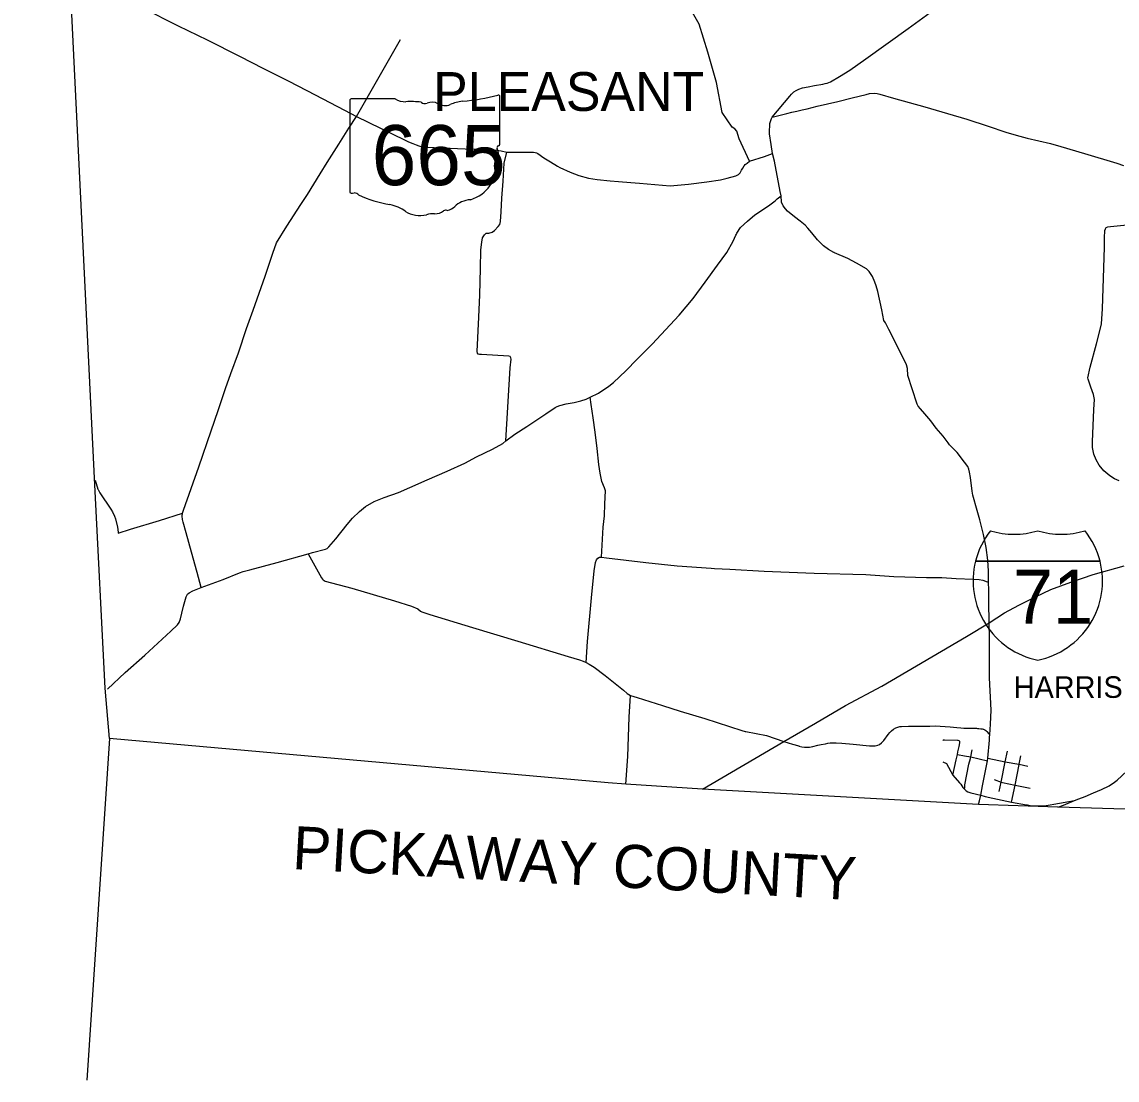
# Model space of a CAD drawing. Extents: x 1755200 to 1902939, y 644115 to 788070.
# Drawn here: x 1757564 to 1782951, y 653104 to 677637 of the extents above; entities that cross this region are included whole.
import ezdxf

# ---------------------------------------------------------------- set-up
doc = ezdxf.new("R2010")
doc.units = 0
for name, color, linetype in [('GM_X_Adjacent_County', 7, 'Continuous'), ('GM_X_Adjacent_County_Text', 7, 'Continuous'), ('GM_X_City_Street', 7, 'Continuous'), ('GM_X_Corporation_Text', 7, 'Continuous'), ('GM_X_County', 7, 'Continuous'), ('GM_X_County_Road', 7, 'Continuous'), ('GM_X_Interstate_Route', 7, 'Continuous'), ('GM_X_Interstate_Shield', 7, 'Continuous'), ('GM_X_State_Route', 7, 'Continuous'), ('GM_X_State_Shield', 7, 'Continuous'), ('GM_X_Township_Road', 7, 'Continuous'), ('GM_X_Township_Text', 7, 'Continuous'), ('GM_X_US_Route', 7, 'Continuous')]:
    doc.layers.add(name, color=color, linetype=linetype)

msp = doc.modelspace()

# ---------------------------------------------------------------- linework, layer by layer
at = {"layer": 'GM_X_Adjacent_County'}
msp.add_line((1759596, 661027), (1759070, 653104), dxfattribs=at)
at = {"layer": 'GM_X_City_Street'}
for points in [[(1779847, 661240), (1779853, 661239), (1779883, 661223), (1779909, 661206), (1779930, 661187), (1779979, 661133), (1780000, 661107)], [(1778915, 660978), (1778930, 660991), (1778950, 660994), (1779248, 660981), (1779262, 660981), (1779284, 660976)], [(1779263, 660711), (1779287, 660836), (1779305, 660926), (1779302, 660952), (1779284, 660976)], [(1779741, 659492), (1779762, 659575), (1779789, 659710), (1779832, 659924), (1779945, 660504), (1779955, 660564), (1779994, 660984), (1779997, 661054)], [(1779147, 660174), (1779218, 660526), (1779253, 660654), (1779263, 660711)], [(1779253, 660654), (1779413, 660623)], [(1779413, 660623), (1779561, 660595), (1779945, 660504)], [(1779551, 660558), (1779561, 660595), (1779563, 660601), (1779594, 660760)], [(1780218, 659794), (1780262, 660012), (1780354, 660480), (1780407, 660730)], [(1780679, 660419), (1780680, 660423), (1780681, 660430), (1780720, 660624)], [(1778914, 660484), (1778995, 660444), (1779147, 660174), (1779301, 659998), (1779316, 659981)], [(1779413, 659848), (1779419, 659887), (1779421, 659949), (1779516, 660426), (1779551, 660558)], [(1779955, 660564), (1780354, 660480), (1780676, 660432)], [(1780506, 659550), (1780588, 659944), (1780679, 660419)], [(1780676, 660432), (1780676, 660432), (1780681, 660430), (1780880, 660384)], [(1780101, 660073), (1780262, 660012), (1780292, 660006)], [(1779316, 659981), (1779328, 659966), (1779352, 659929), (1779378, 659888), (1779413, 659848)], [(1779413, 659848), (1779453, 659809), (1779488, 659785), (1779561, 659760), (1779789, 659710)], [(1780292, 660006), (1780588, 659944), (1780937, 659869)], [(1779789, 659710), (1779892, 659678), (1780069, 659640), (1780506, 659550), (1780854, 659487), (1780872, 659483)]]:
    msp.add_lwpolyline(points, dxfattribs=at)
at = {"layer": 'GM_X_County'}
msp.add_lwpolyline([(1784956, 659328), (1781576, 659434), (1779741, 659492), (1773339, 659850), (1771560, 659962), (1771157, 659994), (1759596, 661027), (1759497, 662188), (1759258, 666902), (1758681, 678614), (1758672, 678766), (1758400, 683790), (1758170, 688397), (1758072, 690399), (1757841, 694414), (1757825, 694698), (1757564, 699226), (1758151, 699596), (1759102, 700215), (1763614, 703154)], dxfattribs=at)
at = {"layer": 'GM_X_County_Road'}
for points in [[(1774956, 675429), (1775362, 675913), (1775404, 675965), (1775460, 676012), (1775514, 676048), (1775572, 676079), (1775656, 676108), (1775793, 676134), (1775936, 676163), (1776130, 676195), (1776187, 676207), (1776227, 676216), (1776304, 676244), (1776516, 676373), (1776754, 676520), (1777127, 676778), (1778110, 677485), (1778787, 677975)], [(1761718, 664522), (1761629, 664869), (1761494, 665341), (1761375, 665791), (1761303, 666042), (1761289, 666098), (1761282, 666179), (1761289, 666249), (1761307, 666319), (1761667, 667325), (1761951, 668157), (1762115, 668630), (1762282, 669135), (1762409, 669489), (1762581, 669962), (1762769, 670526), (1762924, 670951), (1763200, 671744), (1763378, 672275), (1763468, 672511), (1763705, 672898), (1764033, 673400), (1764187, 673633), (1764477, 674115), (1764641, 674378), (1764908, 674799), (1765145, 675172), (1765320, 675443)], [(1775143, 673702), (1775006, 674406), (1774965, 674582)], [(1774127, 672717), (1774135, 672735), (1774225, 672873), (1774380, 673020), (1774555, 673162), (1774867, 673370), (1775024, 673487), (1775070, 673535), (1775162, 673604)], [(1776387, 672291), (1776262, 672357), (1776143, 672446), (1776006, 672587), (1775875, 672747), (1775780, 672854), (1775718, 672924), (1775682, 672955), (1775601, 673017), (1775473, 673119), (1775314, 673250), (1775264, 673305), (1775207, 673375), (1775170, 673458), (1775162, 673604), (1775143, 673702)], [(1783002, 666997), (1782890, 667046), (1782780, 667109), (1782641, 667230), (1782535, 667360), (1782467, 667486), (1782408, 667615), (1782384, 667769), (1782377, 667901), (1782412, 668652), (1782429, 668886), (1782404, 669000), (1782343, 669165), (1782281, 669354), (1782273, 669384), (1782325, 669630), (1782473, 670172), (1782582, 670601), (1782588, 670635), (1782611, 670984), (1782644, 671937), (1782659, 672414), (1782657, 672628), (1782664, 672804), (1782683, 672840), (1782701, 672870), (1782735, 672884), (1782799, 672895), (1783258, 672938)], [(1764301, 665332), (1764301, 665332), (1764605, 665414), (1764637, 665432), (1764681, 665467), (1764841, 665654), (1765105, 665985), (1765231, 666134), (1765390, 666285), (1765525, 666400), (1765726, 666517), (1765965, 666611), (1766290, 666724), (1766553, 666846), (1766958, 667023), (1767424, 667224), (1767830, 667409), (1768105, 667551), (1768475, 667728), (1768710, 667866), (1768782, 667924), (1768990, 668078), (1769267, 668258), (1769708, 668551), (1769929, 668698), (1769969, 668723), (1770035, 668747), (1770182, 668782), (1770362, 668814), (1770522, 668849), (1770641, 668890), (1770737, 668933), (1770926, 669032), (1771171, 669190), (1771276, 669273), (1771560, 669549), (1771828, 669820), (1772171, 670165), (1772801, 670835), (1773122, 671225), (1773401, 671599), (1773692, 672000), (1773906, 672294), (1774048, 672554), (1774113, 672689), (1774127, 672717)], [(1779970, 664753), (1779970, 664754), (1779968, 664903), (1779958, 665156), (1779916, 665455), (1779856, 665754), (1779767, 666089), (1779704, 666310), (1779605, 666661), (1779588, 666760), (1779552, 667071), (1779533, 667201), (1779517, 667271), (1779492, 667327), (1779415, 667432), (1779242, 667654), (1779065, 667828), (1779034, 667876), (1778917, 668033), (1778760, 668219), (1778633, 668388), (1778498, 668548), (1778395, 668665), (1778341, 668727), (1778320, 668774), (1778204, 669129), (1778102, 669437), (1778095, 669601), (1778068, 669689), (1777883, 670067), (1777658, 670508), (1777579, 670661), (1777547, 670717), (1777497, 670964), (1777408, 671388), (1777367, 671520), (1777338, 671600), (1777278, 671733), (1777201, 671850), (1777142, 671913), (1776909, 672047), (1776709, 672149), (1776398, 672285), (1776389, 672290), (1776387, 672291)], [(1759547, 662165), (1759958, 662552), (1760412, 662957), (1761016, 663510), (1761167, 663661), (1761210, 663716), (1761240, 663796), (1761273, 663926), (1761307, 664090), (1761374, 664310), (1761405, 664366), (1761441, 664402), (1761529, 664445), (1761718, 664522), (1762230, 664712), (1762605, 664861), (1762694, 664895), (1762844, 664931), (1763478, 665102), (1764200, 665305), (1764301, 665332)], [(1764200, 665305), (1764508, 664749), (1764532, 664717), (1764549, 664699), (1764595, 664670), (1765211, 664507), (1766199, 664214), (1766592, 664095), (1766738, 664031), (1766806, 663977), (1766832, 663961), (1767023, 663901), (1768012, 663600), (1769058, 663279), (1770224, 662926), (1770486, 662848), (1770574, 662819), (1770642, 662787), (1770716, 662746), (1770829, 662675), (1771082, 662480), (1771512, 662142), (1771595, 662069), (1771631, 662047), (1771673, 662023), (1771823, 661973), (1772416, 661788), (1772823, 661656), (1773396, 661485), (1774251, 661212), (1774330, 661187)], [(1779992, 662480), (1779997, 663084), (1779995, 663356), (1779983, 663706), (1779979, 664192), (1779975, 664462), (1779970, 664647), (1779970, 664753)], [(1780000, 661107), (1780016, 661353), (1780029, 661677), (1779992, 662426), (1779992, 662464), (1779992, 662480)], [(1774330, 661187), (1774345, 661182), (1774826, 661093), (1775224, 660950), (1775426, 660892), (1775570, 660850)], [(1775570, 660850), (1775573, 660849), (1775645, 660831), (1775702, 660823), (1775752, 660820), (1775821, 660824), (1775899, 660840), (1776014, 660865), (1776093, 660882), (1776188, 660900), (1776247, 660912), (1776301, 660920), (1776345, 660924), (1776376, 660926), (1776437, 660926), (1776574, 660914), (1776830, 660891), (1777209, 660855), (1777290, 660850), (1777340, 660853), (1777402, 660866), (1777444, 660886), (1777493, 660920), (1777545, 660976), (1777644, 661113), (1777682, 661165), (1777719, 661203), (1777770, 661242), (1777821, 661270), (1777865, 661289), (1777912, 661301), (1777957, 661305), (1778112, 661307), (1778614, 661313), (1778735, 661315), (1778852, 661310), (1779083, 661293), (1779238, 661278), (1779326, 661271), (1779401, 661265), (1779473, 661263), (1779690, 661259), (1779718, 661258), (1779746, 661257)], [(1779746, 661257), (1779747, 661257), (1779794, 661251), (1779825, 661246), (1779847, 661240)], [(1779997, 661054), (1780000, 661107), (1780000, 661107)], [(1780872, 659483), (1780936, 659470), (1781001, 659463), (1781105, 659460), (1781183, 659463), (1781304, 659472), (1781396, 659484), (1781481, 659498), (1781967, 659586)]]:
    msp.add_lwpolyline(points, dxfattribs=at)
at = {"layer": 'GM_X_Interstate_Route'}
msp.add_lwpolyline([(1773339, 659850), (1775224, 660950), (1775957, 661376), (1776652, 661789), (1777498, 662236), (1779457, 663388), (1779983, 663706), (1780338, 663933), (1780676, 664112), (1781059, 664311), (1781412, 664474), (1781875, 664650), (1782399, 664828), (1783114, 665027)], dxfattribs=at)
at = {"layer": 'GM_X_Interstate_Shield'}
for p, q in [((1779669, 665137), (1782554, 665137)), ((1782554, 665137), (1779669, 665137)), ((1782554, 665137), (1779669, 665137))]:
    msp.add_line(p, q, dxfattribs=at)
for centre, start, end in [((1781487, 664677), 141.669, 165.8066), ((1780564, 667633), 253.0091, 286.9909), ((1781659, 667633), 253.0091, 286.9909), ((1780737, 664677), 14.1934, 38.331), ((1781487, 664677), 165.8066, 258.463), ((1780737, 664677), 281.537, 14.1934)]:
    msp.add_arc(centre, 1875, start, end, dxfattribs=at)
at = {"layer": 'GM_X_State_Route'}
for points in [[(1760356, 677962), (1761185, 677549), (1761857, 677219), (1762607, 676839), (1763166, 676560), (1763750, 676259), (1764361, 675943), (1765045, 675589), (1765320, 675443), (1766432, 674900), (1766528, 674860), (1766624, 674819), (1766707, 674783), (1766766, 674760), (1766836, 674741), (1766930, 674733), (1767316, 674714), (1767839, 674697), (1768338, 674685), (1768516, 674670), (1768673, 674646), (1768805, 674613), (1768981, 674615), (1769337, 674616), (1769425, 674616), (1769459, 674611), (1769494, 674600), (1769524, 674583), (1769666, 674488), (1769814, 674389), (1769977, 674293), (1770036, 674265)], [(1771677, 673914), (1771877, 673898), (1772593, 673840), (1773013, 673876), (1773444, 673930), (1773760, 673979), (1773909, 674015), (1774111, 674070), (1774175, 674101), (1774214, 674140), (1774245, 674198), (1774272, 674244), (1774303, 674298), (1774331, 674330), (1774372, 674364), (1774429, 674407), (1774779, 674519), (1774965, 674582), (1774929, 674798), (1774892, 675044), (1774891, 675067), (1774898, 675281), (1774939, 675401), (1774956, 675429), (1775298, 675511), (1775413, 675541), (1775530, 675569), (1775648, 675596), (1775766, 675623), (1775997, 675685), (1776236, 675741), (1776474, 675794), (1776813, 675876)], [(1776813, 675876), (1777131, 675954), (1777214, 675975), (1777318, 675984), (1777389, 675973), (1777453, 675960), (1777771, 675870), (1778493, 675666), (1779017, 675513)], [(1779017, 675513), (1779470, 675381), (1779964, 675221), (1780368, 675082), (1780611, 675007), (1780865, 674940), (1781405, 674816), (1781645, 674748), (1782195, 674586), (1782945, 674365), (1783098, 674311)], [(1770036, 674265), (1770273, 674153), (1770470, 674076), (1770695, 674012), (1770898, 673985), (1771197, 673953), (1771395, 673937), (1771677, 673914)]]:
    msp.add_lwpolyline(points, dxfattribs=at)
at = {"layer": 'GM_X_State_Shield'}
for p, q in [((1765162, 675817), (1765162, 673703)), ((1766216, 675853), (1765196, 675853)), ((1768642, 674800), (1768642, 675905)), ((1768642, 674800), (1768642, 674800))]:
    msp.add_line(p, q, dxfattribs=at)
for centre, major_axis, start_param, end_param in [((1765202, 675821), (40.3, 0), 1.712693, 3.28349), ((1766458, 676098), (391, 0), 4.042523, 4.731795), ((1767403, 678734), (3691, 0), 4.814394, 5.042369), ((1768604, 675910), (38.7, 0), 6.141152, 7.989035), ((1766588, 674667), (1404, 0), 1.404758, 1.657858), ((1766907, 675832), (113, 0), 3.836095, 5.185415), ((1767072, 675588), (235, 0), 0.950623, 2.079405), ((1767375, 675923), (282, 0), 4.081561, 5.145723), ((1767873, 675208), (743, 0), 1.699011, 2.107814), ((1768601, 674796), (41.5, 0), 5.05454, 6.418171), ((1768633, 674719), (60, 0), 1.883978, 3.671073), ((1768252, 674579), (360, 0), 5.934695, 6.695948), ((1767609, 674197), (923, 0), 5.101752, 6.440018), ((1768781, 674337), (262, 0), 2.387724, 3.262537), ((1765202, 673699), (40.7, 0), 3.00124, 4.508301), ((1765208, 673915), (310, 0), 4.665946, 4.897461), ((1765272, 673581), (112, 0), 0.519207, 1.627899), ((1766685, 675480), (2665, 0), 4.195997, 4.488961), ((1765890, 672754), (834, 0), 0.823519, 1.323587), ((1767392, 673208), (79.4, 0), 1.147584, 2.315152), ((1767358, 673499), (298, 0), 4.937069, 5.64225), ((1767999, 673110), (506, 0), 1.647645, 2.488434), ((1766792, 673571), (529, 0), 4.026481, 4.996735), ((1767098, 672840), (435, 0), 1.495662, 1.94098), ((1767137, 673413), (282, 0), 4.691044, 5.507374)]:
    msp.add_ellipse(centre, major_axis=major_axis, ratio=0.8, start_param=start_param, end_param=end_param, dxfattribs=at)
at = {"layer": 'GM_X_Township_Road'}
for points in [[(1774429, 674407), (1774188, 674926), (1774139, 675101), (1774091, 675155), (1774025, 675200), (1773798, 675535), (1773663, 676229), (1773462, 676936), (1773264, 677586), (1772665, 678633), (1771860, 679950), (1771386, 680739), (1770061, 682979), (1769620, 683702), (1769410, 684045), (1769171, 684488)], [(1765320, 675443), (1766343, 677226)], [(1768782, 667924), (1768885, 669618), (1768902, 669820), (1768894, 669852), (1768879, 669876), (1768851, 669884), (1768219, 669922), (1768169, 669926), (1768139, 669936), (1768127, 669957), (1768117, 669999), (1768155, 670792), (1768179, 671312), (1768197, 671923), (1768200, 672352), (1768222, 672528), (1768242, 672630), (1768285, 672702), (1768327, 672737), (1768389, 672737), (1768461, 672760), (1768520, 672800), (1768603, 672892), (1768639, 672943), (1768659, 673013), (1768677, 673235), (1768691, 673554), (1768716, 673942), (1768745, 674359), (1768805, 674613)], [(1770996, 665230), (1771039, 665921), (1771065, 666186), (1771077, 666462), (1771093, 666764), (1771068, 666837), (1771009, 666979), (1770968, 667178), (1770940, 667377), (1770901, 667750), (1770849, 668125), (1770808, 668454), (1770760, 668767), (1770737, 668933)], [(1759265, 667013), (1759325, 666804), (1759328, 666798)], [(1759328, 666798), (1759369, 666719), (1759372, 666715), (1759626, 666342), (1759664, 666282), (1759709, 666178)], [(1759709, 666178), (1759734, 666118), (1759737, 666113), (1759777, 665920), (1759792, 665810), (1759798, 665786), (1760083, 665878), (1760753, 666081), (1761289, 666249)], [(1770642, 662787), (1770675, 663273), (1770765, 664287), (1770830, 664907), (1770857, 665105), (1770884, 665169), (1770914, 665205), (1770952, 665225), (1770996, 665230), (1771116, 665211), (1772026, 665102), (1772750, 665027), (1773538, 664969), (1773618, 664968), (1773976, 664951), (1774772, 664906), (1775927, 664855), (1777126, 664825), (1777776, 664781), (1778534, 664755), (1778892, 664756), (1779224, 664731), (1779613, 664718), (1779753, 664707), (1779841, 664692), (1779897, 664671), (1779913, 664666), (1779970, 664647)], [(1771560, 659962), (1771611, 660607), (1771641, 661518), (1771673, 662023)]]:
    msp.add_lwpolyline(points, dxfattribs=at)
at = {"layer": 'GM_X_US_Route'}
for points in [[(1782818, 659962), (1782858, 659989), (1782950, 660058), (1783174, 660262), (1783295, 660401), (1784050, 661158), (1784789, 661898), (1785521, 662721), (1785931, 663218), (1786031, 663343), (1786129, 663449), (1786199, 663506), (1786267, 663559), (1786382, 663639), (1786511, 663709), (1786630, 663762), (1786734, 663801), (1786844, 663844), (1787022, 663911), (1787043, 663919)], [(1782064, 659623), (1782208, 659678), (1782405, 659767), (1782588, 659843), (1782767, 659928), (1782818, 659962)], [(1781576, 659434), (1781708, 659481), (1781967, 659586), (1782064, 659623)]]:
    msp.add_lwpolyline(points, dxfattribs=at)

# ---------------------------------------------------------------- texts
at = {"layer": 'GM_X_Adjacent_County_Text'}
msp.add_text('PICKAWAY COUNTY', height=1000, rotation=356.8216, dxfattribs=at).set_placement((1763818, 657997))
at = {"layer": 'GM_X_Corporation_Text'}
msp.add_text('HARRISBURG', height=500, rotation=0, dxfattribs=at).set_placement((1780555, 661965))
at = {"layer": 'GM_X_Interstate_Shield'}
msp.add_text('71', height=1250, dxfattribs=at).set_placement((1780534, 663684))
at = {"layer": 'GM_X_State_Shield'}
msp.add_text('665', height=1392.2, dxfattribs=at).set_placement((1765672, 673852))
at = {"layer": 'GM_X_Township_Text'}
msp.add_text('PLEASANT', height=900, rotation=0, dxfattribs=at).set_placement((1767095, 675573))

doc.saveas('drawing.dxf')
